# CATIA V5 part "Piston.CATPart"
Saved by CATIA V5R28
Part number: Piston
Bounding box of the stored display mesh (mm): x 0 to 37, y -25 to 25, z -24.976 to 24.976
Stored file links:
  C:\Users\8alex\Desktop\ECL\1A\PE\CATIA\Tuto\Piston.CATPart
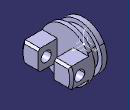
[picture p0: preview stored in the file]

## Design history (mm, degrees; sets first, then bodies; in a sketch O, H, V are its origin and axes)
AxisSystem1: origin (0, 0, 0), X (1, 0, 0), Y (0, 1, 0), Z (0, 0, 1)
Body1 (main body)
  Sketch1 on xy-plane, origin (0, 0, 0), H (1, 0, 0), V (0, 1, 0)
    line L1 (0, 0) -> (0, 23)
    line L2 (0, 23) -> (5, 23)
    line L3 (5, 23) -> (5, 19)
    line L4 (5, 19) -> (14, 19)
    line L5 (14, 19) -> (14, 25)
    line L6 (14, 25) -> (37, 25)
    line L7 (37, 25) -> (37, 0)
    line L8 (37, 0) -> (0, 0)
    axis line L9 (0, 0) -> (37, 0)
    length L1 = 23
    length L2 = 5
    length L4 = 9
    length L8 = 37
    distance L4 L8 = 19
    length L7 = 25
    vertical: L1 V, L3 V, L5 V, L7 V
    horizontal: L2 H, L4 H, L6 H, L8 H, L9 H
  Shaft1: profile Sketch1, axis Sketch1.L9, angle 360
  Sketch2 on face of Shaft1 from Sketch1.L7, origin (37, 0, 0), H (0, 1, 0), V (0, 0, 1)
    line L1 (-30, 30) -> (30, 30)
    line L2 (30, 30) -> (30, 10)
    line L3 (30, 10) -> (8, 10)
    line L4 (8, 10) -> (8, -10)
    line L5 (8, -10) -> (30, -10)
    line L6 (30, -10) -> (30, -30)
    line L7 (30, -30) -> (-30, -30)
    line L8 (-30, -30) -> (-30, -10)
    line L9 (-30, -10) -> (-8, -10)
    line L10 (-8, -10) -> (-8, 10)
    line L11 (-8, 10) -> (-30, 10)
    line L12 (-30, 10) -> (-30, 30)
    reference projected line E1 through (0, 0) direction (0, 1) from edge [ZX plane of AxisSystem1 | YZ plane of AxisSystem1]
    distance L3 H = 10
    distance H L5 = 10
    distance E1 L4 = 8
    distance V L10 = 8
    horizontal: L1 H, L3 H, L5 H, L7 H, L9 H, L11 H
    vertical: L2 V, L4 V, L6 V, L8 V, L10 V, L12 V
  Pocket1: profile Sketch2, direction (-1, 0, 0), length 19
  Chamfer1: length 2, angle 45, on edge [face of Shaft1 from Sketch1.L7 | face of Pocket1 from Sketch2.L9]; edge [face of Shaft1 from Sketch1.L6 | face of Shaft1 from Sketch1.L7] (x2); edge [face of Shaft1 from Sketch1.L7 | face of Pocket1 from Sketch2.L11]; edge [face of Shaft1 from Sketch1.L7 | face of Pocket1 from Sketch2.L3]; edge [face of Shaft1 from Sketch1.L7 | face of Pocket1 from Sketch2.L5]
  Sketch3 on face of Pocket1 from Sketch2.L4, origin (0, 8, 0), H (1, 0, 0), V (0, 0, 1)
    circle A1 centre (29, 0) radius 5
    point P1 (29, 0)
    reference projected line E1 (37, 8) -> (37, -8) from edge [face of Shaft1 from Sketch1.L7 | face of Chamfer1]
    radius A1 = 5
    distance P1 E1 = 8
  Pocket2: profile Sketch3, direction (0, 1, 0), length 160, mirrored extent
